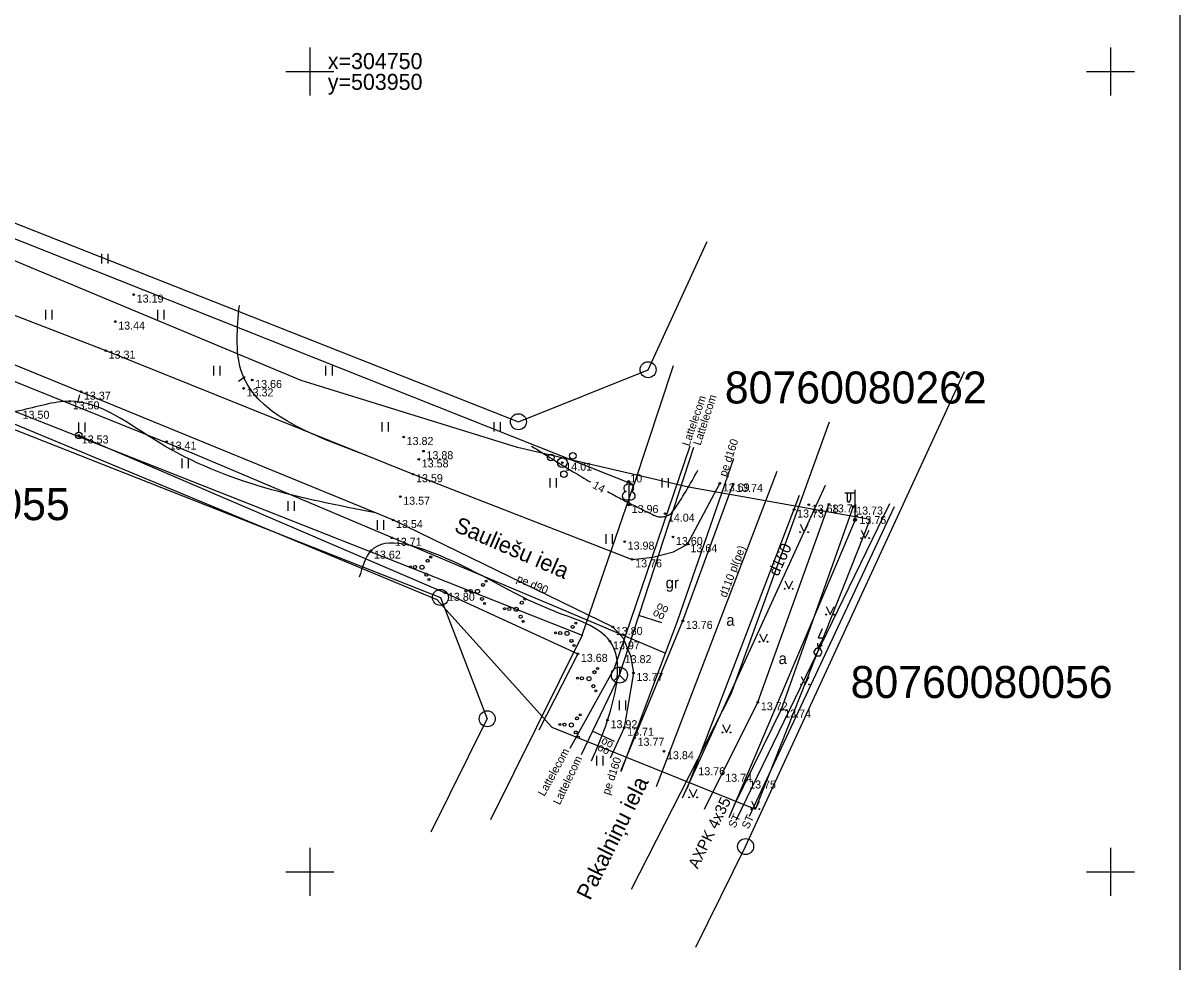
# Model space of a CAD drawing. Extents: x 503353 to 504004, y 304662 to 305049.
# Drawn here: x 503932.1 to 504004.3, y 304694.4 to 304753 of the extents above; entities that cross this region are included whole.
import ezdxf

# ---------------------------------------------------------------- set-up
doc = ezdxf.new("R2010")
doc.units = 0
for name, color, linetype in [('13', 7, 'Continuous'), ('24', 7, 'Continuous'), ('59', 7, 'Continuous'), ('APGR_ELEM_####_####_#', 7, 'Continuous'), ('APGR_SARK_####_####_#', 7, 'Continuous'), ('APGS_ELEM_####_####_#', 7, 'Continuous'), ('APGS_VADP_ZSPR_####_#', 7, 'Continuous'), ('APGS_VADP_ZSPR_TKST_#', 7, 'Continuous'), ('CELI_CMAL_####_####_#', 7, 'Continuous'), ('CELI_CSEG_####_TKST_#', 7, 'Continuous'), ('CELI_IELA_####_TKST_#', 7, 'Continuous'), ('CELI_SEGL_####_####_#', 7, 'Continuous'), ('CKOM_ELEM_####_####_#', 7, 'Continuous'), ('ELEK_VADP_VSPR_####_#', 7, 'Continuous'), ('ELEK_VADP_VSPR_TKST_#', 7, 'Continuous'), ('ELEK_VADP_ZSPR_####_#', 7, 'Continuous'), ('ELEK_VADP_ZSPR_TKST_#', 7, 'Continuous'), ('GAZE_VADP_VSP2_####_#', 7, 'Continuous'), ('GAZE_VADP_VSP2_TKST_#', 7, 'Continuous'), ('GEOD_ELEM_####_####_#', 7, 'Continuous'), ('GEOD_KORD_####_TKST_#', 7, 'Continuous'), ('Level 17', 7, 'Continuous'), ('NORB_ELEM_####_####_#', 7, 'Continuous'), ('NORB_ZOGS_SBST_####_#', 7, 'Continuous'), ('RAMI_PLAN_####_TKST_#', 7, 'Continuous'), ('RAMI_UZMR_####_####_#', 7, 'Continuous'), ('RELJ_AATZ_####_TKST_#', 7, 'Continuous'), ('RELJ_ELEM_####_####_#', 7, 'Continuous'), ('RELJ_HORZ_####_TKST_#', 7, 'Continuous'), ('RELJ_HORZ_PAMT_####_#', 7, 'Continuous'), ('RELJ_HORZ_RESN_####_#', 7, 'Continuous'), ('SAKK_ELEM_####_####_#', 7, 'Continuous'), ('SAKK_ELEM_####_TKST_#', 7, 'Continuous'), ('SAKK_IZVK_####_TKST_#', 7, 'Continuous'), ('SAKK_KKAN_####_####_#', 7, 'Continuous'), ('SAKK_KKAN_####_TKST_#', 7, 'Continuous'), ('SAKT_VADP_KABE_TKST_#', 7, 'Continuous'), ('SKAN_VADP_SPDK_####_I', 7, 'Continuous'), ('SKAN_VADP_SPDK_TKST_I', 7, 'Continuous'), ('TERT_DIAM_####_TKST_#', 7, 'Continuous'), ('TERT_ELEM_####_####_#', 7, 'Continuous'), ('TERT_KONT_####_####_#', 7, 'Continuous'), ('UDTK_VADP_UDEN_####_#', 7, 'Continuous'), ('UDTK_VADP_UDEN_TKST_#', 7, 'Continuous')]:
    doc.layers.add(name, color=color, linetype=linetype)

msp = doc.modelspace()

# ---------------------------------------------------------------- linework, layer by layer
at = {"layer": '13'}
msp.add_line((503967.009, 304714.779), (503970.226, 304724.182), dxfattribs=at)
at = {"layer": '24'}
for p, q in [((503970.226, 304724.182), (503906.256, 304749.582)), ((503901.514, 304740.605), (503967.009, 304714.779)), ((503972.686, 304731.609), (503970.226, 304724.182)), ((503982.425, 304728.101), (503976.275, 304711.091)), ((503967.009, 304714.779), (503961.279, 304703.257)), ((503976.275, 304711.091), (503970.052, 304698.895))]:
    msp.add_line(p, q, dxfattribs=at)
at = {"layer": 'APGR_ELEM_####_####_#'}
for centre in [(503971.12, 304731.37), (503963.02, 304728.12), (503958.15, 304717.14), (503961.07, 304709.56), (503977.21, 304701.58)]:
    msp.add_circle(centre, 0.5, dxfattribs=at)
at = {"layer": 'APGR_SARK_####_####_#'}
for p, q in [((503905.626, 304750.753), (503963.024, 304728.12)), ((503901.046, 304739.66), (503958.153, 304717.141)), ((503971.117, 304731.368), (503974.812, 304739.384)), ((503963.024, 304728.12), (503971.117, 304731.368)), ((503977.208, 304701.58), (503990.886, 304731.257)), ((503958.153, 304717.141), (503961.074, 304709.562)), ((503957.575, 304702.49), (503961.074, 304709.562)), ((503974.095, 304695.289), (503977.208, 304701.58))]:
    msp.add_line(p, q, dxfattribs=at)
at = {"layer": 'APGS_ELEM_####_####_#'}
for p, q in [((503984.043, 304723.65), (503983.408, 304723.645)), ((503983.543, 304723.646), (503983.543, 304723.254)), ((503983.753, 304723.648), (503983.753, 304723.254)), ((503984.043, 304721.983), (503984.043, 304723.866))]:
    msp.add_line(p, q, dxfattribs=at)
msp.add_circle((503984.043, 304721.983), 0.09, dxfattribs=at)
msp.add_ellipse((503983.648, 304723.254), major_axis=(0, 0.151), ratio=0.695971, start_param=1.570796, end_param=4.712389, dxfattribs=at)
at = {"layer": 'APGS_VADP_ZSPR_####_#'}
msp.add_lwpolyline([(503984.043, 304721.983), (503976.17, 304703.381)], dxfattribs=at)
at = {"layer": 'CELI_CMAL_####_####_#'}
for points in [[(503838.566, 304775.497), (503858.493, 304766.414), (503891.095, 304752.021), (503908.465, 304744.501), (503924.668, 304737.415), (503937.24, 304732.561), (503956.439, 304724.841), (503970.124, 304719.519), (503971.419, 304719.666), (503972.697, 304719.996), (503973.577, 304720.467), (503975.597, 304724.266)], [(503892.573, 304747.787), (503907.266, 304741.839), (503923.65, 304734.891), (503935.696, 304729.996), (503955.188, 304721.98), (503968.916, 304715.298), (503969.569, 304714.594), (503970.018, 304713.484), (503970.203, 304712.423), (503969.623, 304709.001), (503968.753, 304707.099)], [(503973.563, 304705.212), (503980.582, 304723.535)], [(503974.65, 304703.917), (503977.973, 304710.591), (503982.406, 304722.951)], [(503983.928, 304722.818), (503979.434, 304710.137), (503976.469, 304704.129)]]:
    msp.add_lwpolyline(points, dxfattribs=at)
at = {"layer": 'CELI_SEGL_####_####_#'}
msp.add_lwpolyline([(503969.438, 304706.35), (503973.289, 304715.677), (503976.431, 304724.233)], dxfattribs=at)
at = {"layer": 'CKOM_ELEM_####_####_#'}
msp.add_line((503981.745, 304714.023), (503981.986, 304714.162), dxfattribs=at)
msp.add_lwpolyline([(503981.994, 304715.185), (503981.745, 304714.622), (503982.081, 304714.622), (503981.745, 304714.023), (503981.723, 304714.293)], dxfattribs=at)
msp.add_lwpolyline([(503981.589, 304713.493), (503981.855, 304713.493), (503981.988, 304713.723), (503981.855, 304713.954), (503981.589, 304713.954), (503981.456, 304713.723)], close=True, dxfattribs=at)
at = {"layer": 'ELEK_VADP_VSPR_####_#'}
msp.add_lwpolyline([(503977.461, 304703.483), (503986.505, 304722.817)], dxfattribs=at)
at = {"layer": 'ELEK_VADP_ZSPR_####_#'}
msp.add_lwpolyline([(503986.191, 304722.999), (503983.27, 304716.993), (503976.588, 304703.202)], dxfattribs=at)
at = {"layer": 'GAZE_VADP_VSP2_####_#'}
msp.add_line((503972.968, 304715.726), (503976.469, 304725.811), dxfattribs=at)
for points in [[(503959.241, 304719.129), (503942.635, 304726.153), (503928.043, 304732.023), (503889.109, 304749.041), (503842.207, 304769.449), (503789.961, 304794.142), (503750.626, 304813.288)], [(503963.132, 304717.483), (503959.241, 304719.129)], [(503965.639, 304716.423), (503963.132, 304717.483)], [(503972.194, 304713.65), (503965.639, 304716.423)], [(503969.44, 304706.267), (503972.968, 304715.726)]]:
    msp.add_lwpolyline(points, dxfattribs=at)
at = {"layer": 'GEOD_ELEM_####_####_#'}
for p, q in [((503950, 304751.5), (503950, 304750)), ((504000, 304751.5), (504000, 304750)), ((503948.5, 304750), (503950, 304750)), ((503950, 304750), (503950, 304748.5)), ((503950, 304750), (503951.5, 304750)), ((503998.5, 304750), (504000, 304750)), ((504000, 304750), (504000, 304748.5)), ((504000, 304750), (504001.5, 304750)), ((503950, 304701.5), (503950, 304700)), ((504000, 304701.5), (504000, 304700)), ((503948.5, 304700), (503950, 304700)), ((503950, 304700), (503950, 304698.5)), ((503950, 304700), (503951.5, 304700)), ((503998.5, 304700), (504000, 304700)), ((504000, 304700), (504000, 304698.5)), ((504000, 304700), (504001.5, 304700))]:
    msp.add_line(p, q, dxfattribs=at)
at = {"layer": 'Level 17'}
for points in [[(503969.013, 304712.725), (503973.745, 304726.611)], [(503966.246, 304707.725), (503969.013, 304712.725)]]:
    msp.add_lwpolyline(points, dxfattribs=at)
at = {"layer": 'NORB_ELEM_####_####_#'}
msp.add_circle((503935.559, 304727.262), 0.202, dxfattribs=at)
at = {"layer": 'NORB_ZOGS_SBST_####_#'}
msp.add_lwpolyline([(503935.559, 304727.262), (503958.433, 304717.432), (503966.732, 304713.617), (503964.299, 304708.839)], dxfattribs=at)
at = {"layer": 'RAMI_PLAN_####_TKST_#'}
msp.add_lwpolyline([(504004.329, 304661.504), (503807.145, 304661.504), (503807.145, 304804.108), (504004.329, 304804.108)], close=True, dxfattribs=at)
at = {"layer": 'RAMI_UZMR_####_####_#'}
msp.add_lwpolyline([(503694.651, 304834.724), (503842.283, 304765.867), (503906.257, 304738.482), (503957.92, 304717.007), (503965.115, 304709.043), (503977.816, 304703.921), (503984.983, 304722.003), (503973.641, 304724.027), (503962.956, 304726.507), (503949.451, 304730.69), (503911.592, 304746.502), (503899.782, 304752.825), (503825.923, 304784.828), (503697.433, 304847.709)], dxfattribs=at)
at = {"layer": 'RELJ_ELEM_####_####_#'}
for centre in [(503938.994, 304736.063), (503937.839, 304734.377), (503937.24, 304732.561), (503946.392, 304730.726), (503935.696, 304729.996), (503945.858, 304730.2), (503934.995, 304729.393), (503935.559, 304727.262), (503955.852, 304727.161), (503941.05, 304726.878), (503956.795, 304725.764), (503957.09, 304726.278), (503965.76, 304725.564), (503956.439, 304724.841), (503975.597, 304724.266), (503976.431, 304724.233), (503955.639, 304723.433), (503969.905, 304722.916), (503981.153, 304722.932), (503982.406, 304722.951), (503983.928, 304722.818), (503972.168, 304722.376), (503980.237, 304722.634), (503984.131, 304722.23), (503955.188, 304721.98), (503955.116, 304720.865), (503969.655, 304720.628), (503972.671, 304720.918), (503953.811, 304720.061), (503973.577, 304720.467), (503970.124, 304719.519), (503958.433, 304717.432), (503973.289, 304715.677), (503968.916, 304715.298), (503968.743, 304714.398), (503966.732, 304713.617), (503970.203, 304712.423), (503977.973, 304710.591), (503979.43, 304710.135), (503979.434, 304710.137), (503968.586, 304709.472), (503969.623, 304709.001), (503970.273, 304708.373), (503972.112, 304707.533), (503974.07, 304706.535), (503975.749, 304706.124), (503977.246, 304705.704)]:
    msp.add_circle(centre, 0.05, dxfattribs=at)
at = {"layer": 'RELJ_HORZ_PAMT_####_#'}
for p, q in [((503945.543, 304730.645), (503945.952, 304730.934)), ((503935.603, 304729.789), (503935.485, 304729.303))]:
    msp.add_line(p, q, dxfattribs=at)
for points in [[(503953.528, 304726.011), (503945.681, 304731.368), (503945.59, 304735.374)], [(503954.099, 304722.428), (503940.541, 304726.835), (503934.995, 304729.393), (503931.866, 304728.804), (503927.645, 304728.488)]]:
    msp.add_spline(points, degree=3, dxfattribs=at)
at = {"layer": 'RELJ_HORZ_RESN_####_#'}
for points in [[(503963.835, 304726.598), (503966.436, 304724.996), (503967.511, 304724.355)], [(503968.587, 304723.752), (503969.325, 304723.357), (503970.066, 304722.974), (503970.808, 304722.605), (503971.179, 304722.426), (503971.548, 304722.25), (503971.686, 304722.202), (503971.839, 304722.179), (503972.162, 304722.206), (503972.457, 304722.324), (503972.577, 304722.415), (503972.669, 304722.528), (503974.226, 304725.09)]]:
    msp.add_spline(points, degree=3, dxfattribs=at)
at = {"layer": 'SAKK_ELEM_####_####_#'}
msp.add_line((503969.323, 304712.289), (503969.677, 304711.935), dxfattribs=at)
msp.add_lwpolyline([(503969.323, 304712.789), (503969.323, 304712.289), (503968.969, 304711.935)], dxfattribs=at)
msp.add_circle((503969.323, 304712.289), 0.5, dxfattribs=at)
at = {"layer": 'SAKK_IZVK_####_TKST_#'}
for p, q in [((503971.97, 304715.546), (503970.538, 304716.014)), ((503969.011, 304708.138), (503967.649, 304708.789))]:
    msp.add_line(p, q, dxfattribs=at)
at = {"layer": 'SAKK_KKAN_####_####_#'}
msp.add_lwpolyline([(503966.953, 304707.334), (503969.323, 304712.289), (503973.969, 304726.535)], dxfattribs=at)
at = {"layer": 'SKAN_VADP_SPDK_####_I'}
msp.add_lwpolyline([(503971.645, 304705.322), (503979.18, 304725.027)], dxfattribs=at)
at = {"layer": 'TERT_ELEM_####_####_#'}
for p, q in [((503937, 304738), (503937, 304738.6)), ((503937.4, 304738), (503937.4, 304738.6)), ((503933.5, 304734.5), (503933.5, 304735.1)), ((503933.9, 304734.5), (503933.9, 304735.1)), ((503940.5, 304734.5), (503940.5, 304735.1)), ((503940.9, 304734.5), (503940.9, 304735.1)), ((503944, 304731), (503944, 304731.6)), ((503944.4, 304731), (503944.4, 304731.6)), ((503951, 304731), (503951, 304731.6)), ((503951.4, 304731), (503951.4, 304731.6)), ((503935.559, 304727.464), (503935.559, 304728.064)), ((503935.959, 304727.464), (503935.959, 304728.064)), ((503954.5, 304727.5), (503954.5, 304728.1)), ((503954.9, 304727.5), (503954.9, 304728.1)), ((503961.5, 304727.5), (503961.5, 304728.1)), ((503961.9, 304727.5), (503961.9, 304728.1)), ((503942.011, 304725.223), (503942.011, 304725.823)), ((503942.411, 304725.223), (503942.411, 304725.823)), ((503965, 304724), (503965, 304724.6)), ((503965.4, 304724), (503965.4, 304724.6)), ((503972, 304724), (503972, 304724.6)), ((503972.4, 304724), (503972.4, 304724.6)), ((503948.639, 304722.549), (503948.639, 304723.149)), ((503949.039, 304722.549), (503949.039, 304723.149)), ((503969.905, 304723.263), (503969.905, 304722.916)), ((503969.905, 304722.916), (503970.105, 304722.916)), ((503954.211, 304721.365), (503954.211, 304721.965)), ((503954.611, 304721.365), (503954.611, 304721.965)), ((503980.609, 304721.717), (503980.859, 304721.217)), ((503980.859, 304721.217), (503981.109, 304721.717)), ((503968.5, 304720.5), (503968.5, 304721.1)), ((503968.9, 304720.5), (503968.9, 304721.1)), ((503984.425, 304721.345), (503984.675, 304720.845)), ((503984.675, 304720.845), (503984.925, 304721.345)), ((503979.648, 304718.182), (503979.898, 304717.682)), ((503979.898, 304717.682), (503980.148, 304718.182)), ((503982.244, 304716.567), (503982.494, 304716.067)), ((503982.494, 304716.067), (503982.744, 304716.567)), ((503978.071, 304714.876), (503978.321, 304714.376)), ((503978.321, 304714.376), (503978.571, 304714.876)), ((503980.669, 304712.201), (503980.919, 304711.701)), ((503980.919, 304711.701), (503981.169, 304712.201)), ((503969.322, 304710.094), (503969.322, 304710.694)), ((503969.722, 304710.094), (503969.722, 304710.694)), ((503975.756, 304709.201), (503976.006, 304708.701)), ((503976.006, 304708.701), (503976.256, 304709.201)), ((503967.919, 304706.65), (503967.919, 304707.25)), ((503968.319, 304706.65), (503968.319, 304707.25)), ((503973.682, 304705.153), (503973.932, 304704.653)), ((503973.932, 304704.653), (503974.182, 304705.153)), ((503977.566, 304704.421), (503977.816, 304703.921)), ((503977.816, 304703.921), (503978.066, 304704.421))]:
    msp.add_line(p, q, dxfattribs=at)
for points in [[(503969.905, 304724.416), (503969.905, 304723.263)], [(503969.995, 304724.184), (503969.994, 304724.185)]]:
    msp.add_lwpolyline(points, dxfattribs=at)
for centre, radius in [((503965.046, 304725.888), 0.204), ((503965.76, 304725.564), 0.301), ((503966.421, 304725.989), 0.207), ((503965.863, 304724.836), 0.205), ((503980.609, 304721.216), 0.028), ((503981.109, 304721.216), 0.0263), ((503984.425, 304720.844), 0.028), ((503984.925, 304720.844), 0.0263), ((503957.345, 304719.432), 0.096), ((503957.541, 304719.664), 0.064), ((503956.279, 304719.059), 0.064), ((503956.563, 304719.045), 0.096), ((503956.997, 304719.025), 0.128), ((503957.274, 304718.558), 0.096), ((503957.431, 304718.268), 0.064), ((503960.812, 304717.925), 0.096), ((503961.009, 304718.156), 0.064), ((503959.746, 304717.551), 0.064), ((503960.031, 304717.538), 0.096), ((503960.465, 304717.517), 0.128), ((503960.741, 304717.05), 0.096), ((503963.424, 304717.041), 0.064), ((503979.648, 304717.682), 0.028), ((503980.148, 304717.682), 0.0263), ((503960.899, 304716.761), 0.064), ((503962.161, 304716.436), 0.064), ((503962.446, 304716.422), 0.096), ((503962.88, 304716.402), 0.128), ((503963.227, 304716.809), 0.096), ((503963.156, 304715.935), 0.096), ((503963.314, 304715.645), 0.064), ((503966.602, 304715.533), 0.064), ((503982.243, 304716.066), 0.028), ((503982.743, 304716.066), 0.0263), ((503965.34, 304714.928), 0.064), ((503965.625, 304714.915), 0.096), ((503966.058, 304714.894), 0.128), ((503966.406, 304715.302), 0.096), ((503966.335, 304714.427), 0.096), ((503966.492, 304714.138), 0.064), ((503978.071, 304714.375), 0.028), ((503978.571, 304714.375), 0.0263), ((503967.965, 304712.704), 0.064), ((503966.702, 304712.099), 0.064), ((503966.987, 304712.085), 0.096), ((503967.421, 304712.064), 0.128), ((503967.768, 304712.472), 0.096), ((503967.697, 304711.598), 0.096), ((503967.855, 304711.308), 0.064), ((503980.668, 304711.7), 0.028), ((503981.168, 304711.7), 0.0263), ((503966.871, 304709.812), 0.064), ((503965.608, 304709.207), 0.064), ((503965.893, 304709.194), 0.096), ((503966.327, 304709.173), 0.128), ((503966.674, 304709.581), 0.096), ((503966.603, 304708.706), 0.096), ((503966.761, 304708.417), 0.064), ((503975.756, 304708.7), 0.028), ((503976.256, 304708.7), 0.0263), ((503973.682, 304704.653), 0.028), ((503974.182, 304704.653), 0.0263), ((503977.566, 304703.92), 0.028), ((503978.066, 304703.92), 0.0263)]:
    msp.add_circle(centre, radius, dxfattribs=at)
for centre, major_axis, ratio, start_param, end_param in [((503969.905, 304724.266), (0, -0.15), 0.707107, 3.14537, 5.287485), ((503969.905, 304724.266), (0, -0.15), 0.707107, 0.995701, 3.137816), ((503969.815, 304723.509), (0.307, 0.095), 0.814445, 1.570796, 4.752015), ((503969.777, 304723.971), (-0.039, -0.212), 0.861323, 3.141593, 6.283185), ((503969.995, 304723.509), (-0.307, 0.095), 0.814445, 1.531171, 4.712389), ((503970.033, 304723.971), (0.039, -0.212), 0.861323, 0, 3.141593)]:
    msp.add_ellipse(centre, major_axis=major_axis, ratio=ratio, start_param=start_param, end_param=end_param, dxfattribs=at)
at = {"layer": 'TERT_KONT_####_####_#'}
msp.add_spline([(503967.586, 304706.927), (503968.586, 304709.472), (503968.743, 304714.398), (503965.357, 304716.236), (503958.463, 304719.603), (503953.811, 304720.061), (503953.076, 304718.405)], degree=3, dxfattribs=at)
at = {"layer": 'UDTK_VADP_UDEN_####_#'}
msp.add_lwpolyline([(503973.269, 304704.625), (503982.189, 304724.157)], dxfattribs=at)

# ---------------------------------------------------------------- texts
at = {"layer": '59'}
for s, p in [('80760080262', (503975.91, 304729.257)), ('80760080055', (503918.634, 304721.971)), ('80760080056', (503983.766, 304710.858))]:
    msp.add_text(s, height=2, dxfattribs=at).set_placement(p)
at = {"layer": 'APGS_VADP_ZSPR_TKST_#'}
msp.add_text('AXPK 4x35', height=0.7, rotation=64.05893, dxfattribs=at).set_placement((503974.218, 304700.137))
at = {"layer": 'CELI_CSEG_####_TKST_#'}
for s, p in [('gr', (503972.21, 304717.703)), ('a', (503976, 304715.371)), ('a', (503979.269, 304712.977))]:
    msp.add_text(s, height=0.7, dxfattribs=at).set_placement(p)
at = {"layer": 'CELI_IELA_####_TKST_#'}
for s, rotation, p in [('Sauliešu iela', 336.54899, (503958.942, 304721.297)), ('Pakalniņu iela', 63.75143, (503967.495, 304698.168))]:
    msp.add_text(s, height=1, rotation=rotation, dxfattribs=at).set_placement(p)
at = {"layer": 'ELEK_VADP_VSPR_TKST_#'}
msp.add_text('ST', height=0.5, rotation=64.9293, dxfattribs=at).set_placement((503977.387, 304702.637))
at = {"layer": 'ELEK_VADP_ZSPR_TKST_#'}
msp.add_text('ST', height=0.5, rotation=64.15079, dxfattribs=at).set_placement((503976.545, 304702.69))
at = {"layer": 'GAZE_VADP_VSP2_TKST_#'}
for s, rotation, p in [('pe d160', 71.73513, (503976.005, 304724.651)), ('pe d90', 337.07124, (503962.862, 304718.141)), ('pe d160', 71.73513, (503968.697, 304704.766))]:
    msp.add_text(s, height=0.5, rotation=rotation, dxfattribs=at).set_placement(p)
at = {"layer": 'GEOD_KORD_####_TKST_#'}
for s, p in [('   x=304750', (503950, 304750.15)), ('   y=503950', (503950, 304748.85))]:
    msp.add_text(s, height=1, dxfattribs=at).set_placement(p)
at = {"layer": 'RELJ_AATZ_####_TKST_#'}
for s, p in [(' 13.19', (503938.994, 304735.563)), (' 13.44', (503937.839, 304733.877)), (' 13.31', (503937.24, 304732.061)), (' 13.32', (503945.858, 304729.7)), (' 13.66', (503946.392, 304730.226)), (' 13.50', (503934.995, 304728.893)), (' 13.37', (503935.696, 304729.496)), (' 13.50', (503931.866, 304728.304)), (' 13.53', (503935.559, 304726.762)), (' 13.82', (503955.852, 304726.661)), (' 13.41', (503941.05, 304726.378)), (' 13.58', (503956.795, 304725.264)), (' 13.88', (503957.09, 304725.778)), (' 14.01', (503965.76, 304725.064)), (' 13.59', (503956.439, 304724.341)), (' 13.69', (503975.597, 304723.766)), (' 13.74', (503976.431, 304723.733)), (' 13.57', (503955.639, 304722.933)), (' 13.96', (503969.905, 304722.416)), (' 13.68', (503981.153, 304722.432)), (' 13.71', (503982.406, 304722.451)), (' 13.73', (503983.928, 304722.318)), (' 14.04', (503972.168, 304721.876)), (' 13.73', (503980.237, 304722.134)), (' 13.76', (503984.131, 304721.73)), (' 13.54', (503955.188, 304721.48)), (' 13.71', (503955.116, 304720.365)), (' 13.60', (503972.671, 304720.418)), (' 13.62', (503953.811, 304719.561)), (' 13.98', (503969.655, 304720.128)), (' 13.64', (503973.577, 304719.967)), (' 13.76', (503970.124, 304719.019)), (' 13.80', (503958.433, 304716.932)), (' 13.76', (503973.289, 304715.177)), (' 13.80', (503968.916, 304714.798)), (' 13.97', (503968.743, 304713.898)), (' 13.68', (503966.732, 304713.117)), (' 13.77', (503970.203, 304711.923)), (' 13.72', (503977.973, 304710.091)), (' 13.74', (503979.434, 304709.637)), (' 13.92', (503968.586, 304708.972)), (' 13.71', (503969.623, 304708.501)), (' 13.77', (503970.273, 304707.873)), (' 13.84', (503972.112, 304707.033)), (' 13.76', (503974.07, 304706.035)), (' 13.74', (503975.749, 304705.624)), (' 13.75', (503977.246, 304705.204))]:
    msp.add_text(s, height=0.5, dxfattribs=at).set_placement(p)
at = {"layer": 'RELJ_HORZ_####_TKST_#'}
msp.add_text('14', height=0.5, rotation=330.70423, dxfattribs=at).set_placement((503967.605, 304724.012))
at = {"layer": 'SAKK_ELEM_####_TKST_#'}
msp.add_text('13.82', height=0.5, dxfattribs=at).set_placement((503969.655, 304713.036))
at = {"layer": 'SAKK_IZVK_####_TKST_#'}
for p in [(503971.371, 304716.052), (503971.604, 304716.477), (503968.146, 304708.044), (503967.912, 304707.619)]:
    msp.add_text('oo', height=0.5, rotation=334.44324, dxfattribs=at).set_placement(p)
at = {"layer": 'SAKK_KKAN_####_TKST_#'}
for rotation, p in [(71.93649, (503974.388, 304726.602)), (64.44324, (503965.604, 304704.142))]:
    msp.add_text('Lattelecom', height=0.5, rotation=rotation, dxfattribs=at).set_placement(p)
at = {"layer": 'SAKT_VADP_KABE_TKST_#'}
for rotation, p in [(71.18165, (503973.694, 304726.555)), (61.04323, (503964.639, 304704.681))]:
    msp.add_text('Lattelecom', height=0.5, rotation=rotation, dxfattribs=at).set_placement(p)
at = {"layer": 'SKAN_VADP_SPDK_TKST_I'}
msp.add_text('d110 pl(pe)', height=0.5, rotation=69.07567, dxfattribs=at).set_placement((503976.006, 304717.102))
at = {"layer": 'TERT_DIAM_####_TKST_#'}
msp.add_text('10', height=0.5, dxfattribs=at).set_placement((503970.002, 304724.324))
at = {"layer": 'UDTK_VADP_UDEN_TKST_#'}
msp.add_text('d160', height=0.7, rotation=65.45502, dxfattribs=at).set_placement((503979.24, 304718.422))

doc.saveas('drawing.dxf')
